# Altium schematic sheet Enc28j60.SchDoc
size A4
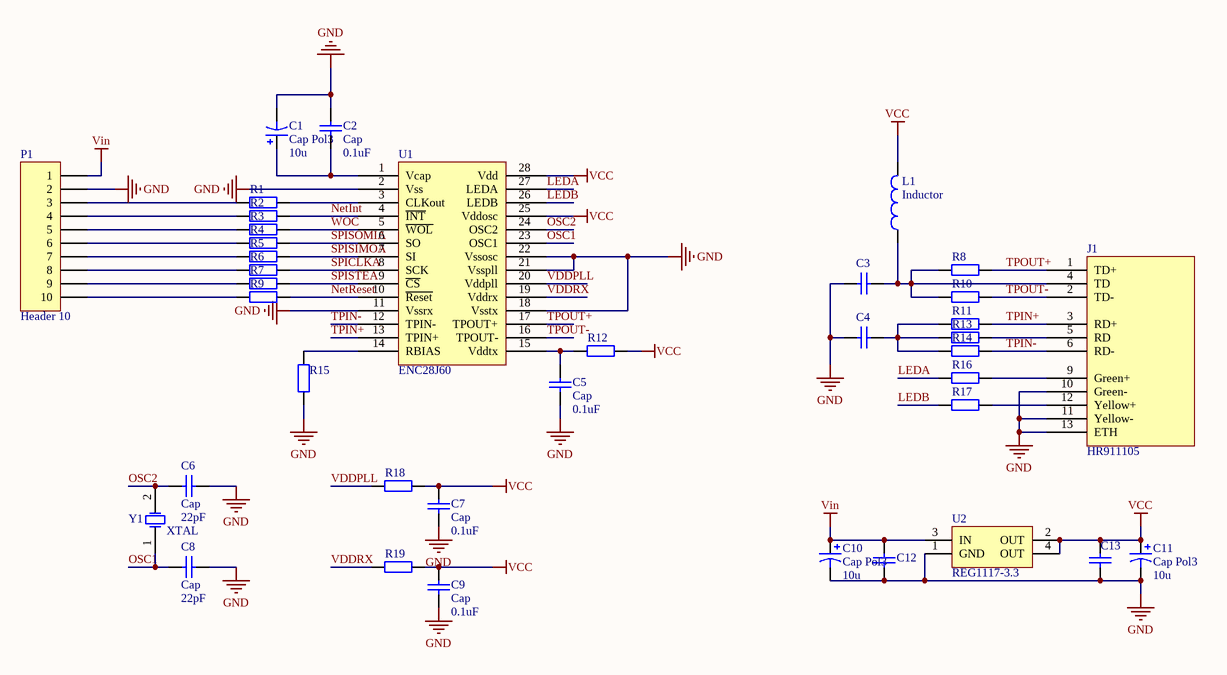
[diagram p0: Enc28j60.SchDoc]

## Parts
C1  Cap Pol3  value 10u  [1812]
C2  Cap  value 0.1uF  [C0805]
C3  Cap  [C0805]  (value not drawn)
C4  Cap  [C0805]  (value not drawn)
C5  Cap  value 0.1uF  [C0805]
C6  Cap  value 22pF  [C0805]
C7  Cap  value 0.1uF  [C0805]
C8  Cap  value 22pF  [C0805]
C9  Cap  value 0.1uF  [C0805]
C10  Cap Pol3  value 10u  [1812]
C11  Cap Pol3  value 10u  [1812]
C12  Cap  [C0805]  (value not drawn)
C13  Cap  [C0805]  (value not drawn)
J1  HR911105  [HR911105A]
L1  Inductor  [AXIAL-0.5]
P1  Header 10  [HDR1X10]
R1  Res2  [C0805]  (value not drawn)
R2  Res2  [C0805]  (value not drawn)
R3  Res2  [C0805]  (value not drawn)
R4  Res2  [C0805]  (value not drawn)
R5  Res2  [C0805]  (value not drawn)
R6  Res2  [C0805]  (value not drawn)
R7  Res2  [C0805]  (value not drawn)
R8  Res2  [C0805]  (value not drawn)
R9  Res2  [C0805]  (value not drawn)
R10  Res2  [C0805]  (value not drawn)
R11  Res2  [C0805]  (value not drawn)
R12  Res2  [C0805]  (value not drawn)
R13  Res2  [C0805]  (value not drawn)
R14  Res2  [C0805]  (value not drawn)
R15  Res2  [C0805]  (value not drawn)
R16  Res2  [C0805]  (value not drawn)
R17  Res2  [C0805]  (value not drawn)
R18  Res2  [C0805]  (value not drawn)
R19  Res2  [C0805]  (value not drawn)
U1  ENC28J60  [DIP-28]
U2  REG1117-3.3  [ZZ311]
Y1  XTAL  [XTAL]

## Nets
GND: C1.2 C2.1 C3.1 C4.1 C5.2 C6.2 C7.2 C8.2 C9.2 C10.2 C11.2 C12.2 C13.2 J1.10(Green-) J1.11(Yellow-) J1.13(ETH) P1.2 R15.1 U1.2(Vss) U1.11(Vssrx) U1.18(Vsstx) U1.21(Vsspll) U1.22(Vssosc) U2.1(GND)
VCC: C7.1 C9.1 C11.1 C13.1 L1.2 R12.2 R18.2 R19.2 U1.25(Vddosc) U1.28(Vdd) U2.2(OUT) U2.4(OUT)
Vin: C10.1 C12.1 P1.1 U2.3(IN)
LEDA: R16.1 U1.27(LEDA)
LEDB: R17.1 U1.26(LEDB)
NetInt: R2.2 U1.4(~{INT})
NetReset: R9.2 U1.10(~{Reset})
OSC1: C8.1 U1.23(OSC1) Y1.1(OSC1)
OSC2: C6.1 U1.24(OSC2) Y1.2(OSC2)
SPICLKA: R6.2 U1.8(SCK)
SPISIMOA: R5.2 U1.7(SI)
SPISOMIA: R4.2 U1.6(SO)
SPISTEA: R7.2 U1.9(~{CS})
TPIN+: J1.3(RD+) R11.2 U1.13(TPIN+)
TPIN-: J1.6(RD-) R14.2 U1.12(TPIN-)
TPOUT+: J1.1(TD+) R8.2 U1.17(TPOUT+)
TPOUT-: J1.2(TD-) R10.2 U1.16(TPOUT-)
VDDPLL: R18.1 U1.20(Vddpll)
VDDRX: R19.1 U1.19(Vddrx)
WOC: R3.2 U1.5(~{WOL})
NetC1_1: C1.1 C2.2 U1.1(Vcap)
NetC3_2: C3.2 J1.4(TD) L1.1 R8.1 R10.1
NetC4_2: C4.2 R11.1 R13.1 R14.1
NetC5_1: C5.1 R12.1 U1.15(Vddtx)
NetJ1_5: J1.5(RD) R13.2
NetJ1_9: J1.9(Green+) R16.2
NetJ1_12: J1.12(Yellow+) R17.2
NetP1_3: P1.3 R1.1
NetP1_4: P1.4 R2.1
NetP1_5: P1.5 R3.1
NetP1_6: P1.6 R4.1
NetP1_7: P1.7 R5.1
NetP1_8: P1.8 R6.1
NetP1_9: P1.9 R7.1
NetP1_10: P1.10 R9.1
NetR1_2: R1.2 U1.3(CLKout)
NetR15_2: R15.2 U1.14(RBIAS)

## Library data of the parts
C1 C10 C11 = Cap Pol3: Polarized Capacitor (Surface Mount)
C2 C5-C9 = Cap: Capacitor
C3 C4 C12 C13 = Cap: Capacitor; Value: 0.1uF
L1 = Inductor: Code_IEC: 1005; Value: 10mH
P1 = Header 10: Header, 10-Pin
R1-R7 R9 R12 R18 R19 = Res2: Resistor; Value: 10K
R8 R10 R11 R14 R16 R17 = Res2: Resistor; Value: 1K
R13 = Res2: Resistor; Value: 0
R15 = Res2: Resistor; Value: 2K
U2 = REG1117-3.3: 800mA and 1A Low Dropout Positive Regulator 2.85V, 3.3V, 5V, and Adjustable
Y1 = XTAL: Crystal Oscillator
